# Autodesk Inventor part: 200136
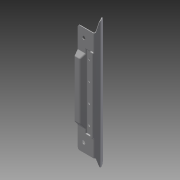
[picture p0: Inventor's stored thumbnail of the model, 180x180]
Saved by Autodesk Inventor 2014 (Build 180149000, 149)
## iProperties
Created: 2007-10
Part Number: 200136
Document SubType Name: Modeling
Designer: TH
Density: 7.85 g/cm^3
Mass: 540.598 g
Surface Area: 646.996 cm^2
Volume: 68.8659 cm^3
Material: Steel
Description: TOP BACK PLATE
Appearance: Steel
Component Category: Lower Component
Author: TH
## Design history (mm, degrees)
sketch "Sketch1"
  geometry: L1 (-2.429, 14.601)-(-8.386, -0.274); L2 (-8.386, -0.274)-(-13.529, -0.176); L3 (-17.529, 4.591)-(-13.529, -0.176); L4 (-30.568, 4.753)-(-41.142, -7.902); L5 (-41.142, -7.902)-(-56.25, -7.902); L6 (0, -18.367)-(0, 39.488) reference; L7 (-67.614, 0)-(11.932, 0) reference; L8 (-0.387, 13.783)-(-6.909, -2.502); L9 (-6.909, -2.502)-(-14.572, -2.357); L10 (-14.572, -2.357)-(-18.566, 2.404); L11 (-18.566, 2.404)-(-29.55, 2.54); L12 (-29.55, 2.54)-(-40.113, -10.102); L13 (-40.113, -10.102)-(-56.25, -10.102); L14 (-56.25, -7.902)-(-56.25, -10.102); L15 (-30.568, 4.753)-(-17.529, 4.591); L16 (-2.656, 17.284)-(-10.494, 30.073); L17 (-0.78, 18.433)-(-8.618, 31.223); L18 (-8.618, 31.223)-(-10.494, 30.073); A1 r 3 centre (-5.214, 15.716) between (-2.429, 14.601) and (-2.656, 17.284); A2 r 5.2 centre (-5.214, 15.716) between (-0.387, 13.783) and (-0.78, 18.433); 14 further points
  constraints: 32 end point, 17 point on line, 4 point on circle, 4 tangent, 2 centre point, 2 parallel, 2 perpendicular
  dimensions: "d5" = 15.66981 vertical distance of point (-2.001, 15.67) point (0, 0); "d6" = 2.0012 distance from line of L6 point (-2.001, 15.67); "d12" = 0.27393 distance from line of L7 L1.end; "d13" = 0.17624 distance from line of L7 L2.end; "d14" = 13.52935 distance from line of L6 L2.end; "d15" = 17.5294 distance from line of L6 L3.start; "d16" = 4.59082 distance from line of L3.start L7; "d17" = 4.75315 distance from line of L7 L4.start; "d18" = 30.56752 distance from line of L6 L4.start; "d19" = 41.14179 distance from line of L6 L4.end; "d20" = 7.90164 distance from line of L7 L4.end; "d21" = 56.25 distance from line of L6 L5.end; "d36" = 8.38631 distance from line of L6 L1.end; "d41" = 3 radius of A1; "d42" = 5.2 radius of A2; "d84" = 2.2 distance between parallel lines of L4 L12; "d85" = 2.2 distance between parallel lines of L5 L13; "d86" = 2.2 distance between parallel lines of L2 L9 (derived); "d87" = 2.2 distance between parallel lines of L3 L10; "d103" = 2.2 distance between parallel lines of L15 L11; "d106" = 2.50239 vertical distance of point (0, 0) L8.end; "d107" = 2.35685 vertical distance of point (0, 0) L9.end; "d146" = 2.2 distance of L17.end L16.end; "d148" = 15.71633 distance from line of L7 A1.centre; "d149" = 5.2142 distance from line of L6 A2.centre; "d150" = 31.5 deg angle of L6 L17; "d151" = 15 distance of L17.start L17.end
extrude "Extrusion1" new body sketch "Sketch1" stored distance "d26" = 400; taper "d27" = 0 deg
sketch "Sketch2"
  geometry: L1 (56.25, -200)-(56.25, 200) reference; L2 (56.25, 115)-(56.25, 200); L3 (34.539, -200)-(31.672, -200) reference; L4 (31.672, -200)-(31.672, 200) reference; L5 (31.672, 200)-(34.539, 200) reference; L6 (34.539, 200)-(34.539, -200) reference; L7 (16.549, -200)-(13.677, -200) reference; L8 (13.677, 200)-(16.549, 200) reference; L9 (16.549, 200)-(16.549, -200) reference; L10 (56.25, 200)-(-3.75, 200); L11 (56.25, 115)-(-3.75, 115); L12 (-3.75, 200)-(-3.75, 115); L13 (13.677, -200)-(13.677, 200) reference; L14 (8.277, -200)-(5.907, -200) reference; L15 (5.907, -200)-(5.907, 200) reference; L16 (5.907, 200)-(8.277, 200) reference; L17 (8.277, 200)-(8.277, -200) reference; 1 further point
  constraints: 8 end point, 1 parallel, 1 perpendicular, 1 point on line
  dimensions: "d52" = 60 distance of L1.end L10.end; "d110" = 85 distance from line of L11 L5.end
extrude "Extrusion2" cut sketch "Sketch2" stored distance "d49" = 21; taper "d50" = 0 deg
mirror "Mirror1"
sketch "Sketch3"
  geometry: L1 (-4.072, 10.5)-(-1.702, 10.5) reference; L2 (-4.072, 10.5)-(-2.429, 14.601) reference; L3 (-67.5, 0)-(11.25, 0) reference; L4 (0, 39.488)-(0, -18.367) reference; L5 (-56.25, 0)-(-5.907, 0); L6 (-1.702, 10.5)-(-5.907, 0); L7 (-56.25, 0)-(-56.25, 2.2); L8 (-4.072, 10.5)-(-7.396, 2.2); L9 (-56.25, 2.2)-(-7.396, 2.2); 2 further points
  constraints: 10 end point, 3 point on line, 2 parallel, 2 perpendicular
  dimensions: "d54" = 56.25 distance between parallel lines of L4 L7; "d55" = 2.2 distance between parallel lines of L3 L9
extrude "Extrusion3" join sketch "Sketch3" stored distance "d58" = 10; taper "d59" = 0 deg
sketch "Sketch5"
  geometry: L1 (-85, 2.2)-(-85, 0) reference; L2 (0, 2.2)-(-85, 2.2) reference; L3 (-85, 0)-(-97.5, 0); L4 (-97.5, 0)-(-111.404, -10.102); L5 (-85, 2.2)-(-98.215, 2.2); L6 (-98.215, 2.2)-(-115.147, -10.102); L7 (-315, -10.102)-(-85, -10.102) reference; L8 (-115.147, -10.102)-(-111.404, -10.102); L9 (-111.404, -10.102)-(-85, -10.102); L10 (-85, 0)-(-85, -10.102); 1 further point
  constraints: 14 end point, 3 parallel, 2 collinear, 2 point on line, 1 perpendicular
  dimensions: "d62" = 2.2 distance between parallel lines of L6 L4; "d63" = 36 deg angle of L4 L3; "d64" = 12.5 distance from line of L3.end L1
extrude "Extrusion4" cut sketch "Sketch5" distance "d65" = 24.69267; taper "d66" = 0 deg
extrude "Extrusion5" join sketch "Sketch5" distance "d67" = 23.54908; taper "d68" = 0 deg
mirror "Mirror2"
workplane "Work Plane1"
sketch "Sketch8"
  geometry: L1 (-46.86, -12.127)-(-36.844, -6.356) reference; L2 (-36.844, -6.356)-(-46.86, -12.127) reference; L3 (-36.844, -6.356)-(-39.902, -14.683) reference; L4 (-39.902, -14.683)-(-36.844, -6.356) reference; L5 (-46.86, -12.127)-(-39.902, -14.683) reference; L6 (-36.933, -6.599)-(-39.902, -14.683); L7 (-39.902, -14.683)-(-50.02, -10.967); L8 (-36.844, -6.356)-(-43.943, -10.447); L9 (-32.97, -4.124)-(-32.586, -3.902) reference; L10 (-32.586, -3.902)-(-32.97, -4.124) reference; L11 (-35.454, -5.555)-(-32.97, -4.124) reference; L12 (-32.97, -4.124)-(-35.454, -5.555) reference; L13 (-36.844, -6.356)-(-35.454, -5.555) reference; L14 (-35.454, -5.555)-(-36.844, -6.356) reference; A1 r 7.2 centre (-47.538, -4.208) between (-50.02, -10.967) and (-43.943, -10.447) reference; A2 r 7.2 centre (-47.538, -4.208) between (-50.02, -10.967) and (-43.943, -10.447) reference; A3 r 7.2 centre (-47.538, -4.208) between (-50.02, -10.967) and (-43.943, -10.447); 2 further points
  constraints: 6 end point, 2 collinear, 2 point on circle, 2 tangent, 1 centre point, 1 coincident, 1 perpendicular
extrude "Extrusion8" cut sketch "Sketch8" stored distance "d75" = 215; taper "d76" = 0 deg
sketch "Sketch9"
  geometry: L1 (0, 0)-(2.872, 0) reference; L2 (0, 0)-(-0.171, 0.204) reference; L3 (-14.306, 0)-(-12.172, 2.553) reference; L4 (-12.172, 2.553)-(0.866, 2.391) reference; L5 (0.866, 2.391)-(2.872, 0) reference; L6 (2.872, 0)-(4.718, -2.2) reference; L7 (4.718, -2.2)-(1.846, -2.2) reference; L8 (3.824, -4.557)-(1.846, -2.2) reference; L9 (11.486, -4.702)-(3.824, -4.557) reference; L10 (12.488, -2.2)-(11.486, -4.702) reference; L11 (12.488, -2.2)-(10.119, -2.2) reference; L12 (10.009, -2.474)-(10.119, -2.2) reference; L13 (4.866, -2.376)-(10.009, -2.474) reference; L14 (4.718, -2.2)-(4.866, -2.376) reference; L15 (10.119, -2.2)-(4.718, -2.2) reference; L16 (-14.306, 0)-(-11.439, 0) reference; L17 (-37.855, 0)-(-14.306, 0) reference; L18 (-37.855, -2.2)-(-37.855, 0) reference; L19 (-13.277, -2.2)-(-37.855, -2.2) reference; L20 (1.846, -2.2)-(-13.277, -2.2) reference; L21 (1.846, -2.2)-(0, 0) reference; L22 (0, 0)-(-0.171, 0.204) reference; L23 (-0.171, 0.204)-(-11.154, 0.34) reference; L24 (-11.154, 0.34)-(-11.439, 0) reference; L25 (2.872, 0)-(11, 0) reference; L26 (10.119, -2.2)-(11, 0) reference; L27 (18.008, 11.583)-(12.488, -2.2) reference; L28 (11, 0)-(15.966, 12.401) reference; L29 (-11.439, 0)-(0, 0) reference; L30 (-11.439, 0)-(-13.277, -2.2) reference; L31 (0, 0)-(2.872, 0) reference; L32 (9.777, 29.023)-(17.615, 16.233) reference; L33 (7.901, 27.873)-(9.777, 29.023) reference; L34 (15.739, 15.084)-(7.901, 27.873) reference; A1 r 5.2 centre (13.181, 13.516) between (18.008, 11.583) and (17.615, 16.233) reference; A2 r 3 centre (13.181, 13.516) between (15.966, 12.401) and (15.739, 15.084) reference; 1 further point
extrude "Extrusion9" join sketch "Sketch9" distance "d111" = 2.2; taper "d112" = 0 deg
sketch "Sketch10"
  geometry: L1 (0, 0)-(8.128, 0) reference; L2 (6.282, -2.2)-(8.128, 0) reference; L3 (6.282, -2.2)-(0.881, -2.2) reference; L4 (0, 0)-(0.881, -2.2) reference; L5 (-4.966, 12.401)-(0, 0) reference; L6 (-1.489, -2.2)-(-7.009, 11.583) reference; L7 (-0.487, -4.702)-(-1.489, -2.2) reference; L8 (7.176, -4.557)-(-0.487, -4.702) reference; L9 (9.154, -2.2)-(7.176, -4.557) reference; L10 (9.154, -2.2)-(6.282, -2.2) reference; L11 (6.134, -2.376)-(6.282, -2.2) reference; L12 (0.991, -2.474)-(6.134, -2.376) reference; L13 (0.881, -2.2)-(0.991, -2.474) reference; L14 (0.881, -2.2)-(-1.489, -2.2) reference; L15 (8.128, 0)-(10.134, 2.391) reference; L16 (10.134, 2.391)-(23.172, 2.553) reference; L17 (23.172, 2.553)-(25.305, 0) reference; L18 (25.305, 0)-(48.854, 0) reference; L19 (48.854, 0)-(48.854, -2.2) reference; L20 (48.854, -2.2)-(24.277, -2.2) reference; L21 (24.277, -2.2)-(22.154, 0.34) reference; L22 (22.154, 0.34)-(11.17, 0.204) reference; L23 (11.17, 0.204)-(9.154, -2.2) reference; L24 (24.277, -2.2)-(9.154, -2.2) reference; L25 (3.098, 27.873)-(-4.739, 15.084) reference; L26 (1.222, 29.023)-(3.098, 27.873) reference; L27 (-6.615, 16.233)-(1.222, 29.023) reference; A1 r 3 centre (-2.181, 13.516) between (-4.739, 15.084) and (-4.966, 12.401) reference; A2 r 5.2 centre (-2.181, 13.516) between (-6.615, 16.233) and (-7.009, 11.583) reference; 1 further point
extrude "Extrusion10" join sketch "Sketch10" distance "d113" = 2.2; taper "d114" = 0 deg
mirror "Mirror3"
fillet "Fillet29" dims "d117" = 2.2
fillet "Fillet30" dims "d118" = 2.2
fillet "Fillet32" dims "d120" = 8
fillet "Fillet33" dims "d121" = 2
fillet "Fillet34" dims "d122" = 2.2
fillet "Fillet35" dims "d123" = 2.2
fillet "Fillet36" dims "d124" = 2, "d127" = 3, "d128" = 2
fillet "Fillet39" dims "d129" = 5
fillet "Fillet40" dims "d130" = 2
fillet "Fillet41" dims "d131" = 1
sketch "Sketch12"
  geometry: L1 (0, 0)-(60, 0); L2 (60, 0)-(60, 30); L3 (60, 30)-(0, 30); L4 (0, 30)-(0, 0); 1 further point
  constraints: 8 end point, 2 parallel, 1 horizontal, 1 perpendicular
  dimensions: "d132" = 30 distance between parallel lines of L3 L1; "d133" = 60 distance of L1.start L1.end
extrude "Extrusion11" cut sketch "Sketch12" stored distance "d134" = 6; taper "d135" = 0 deg
sketch "Sketch13"
  geometry: L1 (370, -10.127)-(400, -10.127) reference; L2 (400, -10.127)-(400, 0) reference; L3 (370, -10.127)-(400, 0); 1 further point
  constraints: 2 end point
extrude "Extrusion12" cut sketch "Sketch13" distance "d136" = 6; taper "d137" = 0 deg
fillet "Fillet42" dims "d138" = 6
fillet "Fillet43" dims "d139" = 6
fillet "Fillet44" dims "d140" = 6
fillet "Fillet45" dims "d141" = 6
mirror "Mirror4"
fillet "Fillet46" dims "d142" = 6
fillet "Fillet47" dims "d143" = 6
fillet "Fillet48" dims "d144" = 6
sketch "Sketch14"
  geometry: L1 (0, -59.615)-(0, 0) reference; L2 (18.257, -37.765)-(18.257, 246.535); L3 (67.752, 104.385)-(-12.742, 104.385) reference; L4 (56.25, 384.386)-(56.25, -175.617) reference; 3 further points
  constraints: 2 end point, 1 coincident, 1 midpoint, 1 parallel, 1 point on line
  dimensions: "d152" = 142.15 distance from line of L2.start L3; "d153" = 37.99331 distance between parallel lines of L4 L2
hole "Hole1" sketch "Sketch14" at (18.257, -37.765), (18.257, 246.535) diameter "d154" = 10.5; stored, may be unused: countersink angle "d158" = 90 deg, drill point angle "d160" = 118 deg; dims "d155" = 6, "d156" = 4, "d157" = 2, "d159" = 8
sketch "Sketch15" dims "d171" = 10
  geometry: L1 (0, 230)-(0, 0) reference; L2 (48.156, 115)-(-158.113, 115) reference; L3 (-5.306, 205)-(-3.806, 205); L4 (-5.306, 207.625)-(-3.806, 207.625); L5 (-5.306, 202.375)-(-3.806, 202.375); L6 (-5.306, 147.625)-(-3.806, 147.625); L7 (-5.306, 145)-(-3.806, 145); L8 (-5.306, 142.375)-(-3.806, 142.375); L9 (-5.306, 87.625)-(-3.806, 87.625); L10 (-5.306, 85)-(-3.806, 85); L11 (-5.306, 82.375)-(-3.806, 82.375); L12 (-5.306, 27.625)-(-3.806, 27.625); L13 (-5.306, 25)-(-3.806, 25); L14 (-5.306, 22.375)-(-3.806, 22.375); A1 r 2.625 centre (-5.306, 205) between (-5.306, 207.625) and (-5.306, 202.375); A2 r 2.625 centre (-3.806, 205) between (-3.806, 207.625) and (-3.806, 202.375); A3 r 2.625 centre (-3.806, 145) between (-3.806, 147.625) and (-3.806, 142.375); A4 r 2.625 centre (-5.306, 145) between (-5.306, 147.625) and (-5.306, 142.375); A5 r 2.625 centre (-3.806, 85) between (-3.806, 87.625) and (-3.806, 82.375); A6 r 2.625 centre (-5.306, 85) between (-5.306, 87.625) and (-5.306, 82.375); A7 r 2.625 centre (-3.806, 25) between (-3.806, 27.625) and (-3.806, 22.375); A8 r 2.625 centre (-5.306, 25) between (-5.306, 27.625) and (-5.306, 22.375); 8 further points
  constraints: 24 end point, 16 point on circle, 8 centre point, 8 coincident, 4 tangent, 1 parallel, 1 vertical, 39 other
  dimensions: "d161" = 90 vertical distance of point (-5.306, 205) point (18.503, 115); "d162" = 23.80879 horizontal distance of point (18.503, 115) point (-5.306, 205); "d163" = 5.25 diameter of A1; "d164" = 5.25 diameter of A2 (derived); "d165" = 1.5 distance of L3.start L3.end; "d168" = 60 distance of L4.start L6.start
extrude "Extrusion13" cut sketch "Sketch15" stored distance "d173" = 10; taper "d174" = 0 deg
body "Solid1"
node "Projected Loop2"
node "Projected Loop3"
node "Projected Loop4"
node "Project Cut Edges1"
node "Project Cut Edges2"
node "Project Cut Edges3"
other parameters: "d53" = 2.2
